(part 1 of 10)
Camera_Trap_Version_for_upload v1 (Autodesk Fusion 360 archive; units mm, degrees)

design "Version_for_upload" references "Button_Board_II", "9Vcell", "DHT11 module", "Half_Bridge", "Gears_Motor2", "Control"
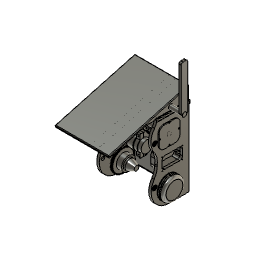
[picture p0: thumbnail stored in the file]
description: Part Number
part number: Contacts
part number: Body
part number: Body003 (Mirror #1)
part number: Contacts (Mirror #1)
part number: Resistor-1206
part number: Body001
part number: Overcoat
part number: Body002
description: KiCad electronic assembly
part number: Button_Board_II 1
part number: PinSocket-01x06_P2.54mm_Horizontal_SMD
parameter "Lower_Gear_Position" = 70
parameter "Inter_Gear_Dist" = 63
parameter "Mid_Gear_Position" = 133 (= "Lower_Gear_Position + Inter_Gear_Dist")
parameter "High_Gear_Position" = 196 (= "Lower_Gear_Position + Inter_Gear_Dist * 2")
parameter "Distance_From_Half_Gear" = 3
parameter "LL_Pin_Length" = 16
parameter "LL_Pin_half_height" = 4.1
parameter "LL_lip_length" = 2
parameter "LL_lip_half_height" = 5
parameter "LL_paper_holding_rod_diam" = 15
parameter "Radius_slidder" = 22.4
parameter "Coil_Diam" = 60
parameter "d371" = 4.1
sketch "Tests" plane through (0, 0, 0) normal (0, 1, 0) x axis (1, 0, 0)
  line L1 (-90.0224, 3) -> (-90.0224, 5)
  line L2 (-29.5204, 3) -> (-20.5451, 3)
  line L3 (-29.5204, 4.2) -> (-29.5204, 3)
  line L4 (-20.5451, 4.2) -> (-29.5204, 4.2)
  line L5 (-20.5451, 3) -> (-20.5451, 4.2)
  line L6 (138, -125) -> (75, -125)
  line L7 (137.8, -100) -> (75, -100)
  line L8 (137.6, -75) -> (75, -75)
  line L9 (137.4, -50) -> (75, -50)
  line L10 (160, -140) -> (55, -140)
  line L11 (160, -35) -> (160, -140)
  line L12 (55, -35) -> (160, -35)
  line L13 (55, -140) -> (55, -35)
  line L14 (250, -180) -> (250, -200)
  line L15 (255, -200) -> (250, -200)
  line L16 (255, -195) -> (255, -200)
  line L17 (260, -195) -> (255, -195)
  line L18 (278.1262, -186.5476) -> (260, -195)
  line L19 (280, -195) -> (260, -195)
  line L20 (278.1262, -180) -> (278.1262, -186.5476)
  line L21 (250, -180) -> (278.1262, -180)
  line L22 (303, -200) -> (300, -200)
  line L23 (303, -180) -> (303, -200)
  line L24 (300, -180) -> (303, -180)
  line L25 (300, -200) -> (300, -180)
  line L26 (306, -197) -> (303, -197)
  line L27 (306, -180) -> (306, -197)
  line L28 (303, -180) -> (306, -180)
  line L29 (303, -197) -> (303, -180)
  line L30 (323, -200) -> (320, -200)
  line L31 (323, -180) -> (323, -200)
  line L32 (320, -180) -> (323, -180)
  line L33 (320, -200) -> (320, -180)
  line L34 (326, -196) -> (323, -196)
  line L35 (326, -180) -> (326, -196)
  line L36 (323, -180) -> (326, -180)
  line L37 (323, -196) -> (323, -180)
  line L38 (250, -145) -> (250, -165)
  line L39 (255, -165) -> (250, -165)
  line L40 (255, -161) -> (255, -165)
  line L41 (260, -161) -> (255, -161)
  line L42 (278.1262, -152.5476) -> (260, -161)
  line L43 (278.1262, -145) -> (278.1262, -152.5476)
  line L44 (250, -145) -> (278.1262, -145)
  line L45 (370.5, -4.2) -> (370.5, -0.1)
  line L46 (375.5, -4.2) -> (370.5, -4.2)
  line L47 (375.5, -17.6) -> (375.5, -4.2)
  line L48 (431, -17.6) -> (375.5, -17.6)
  line L49 (431, 4) -> (431, -17.6)
  line L50 (491.5, -4.2) -> (491.5, -0.1)
  line L51 (486.5, -4.2) -> (491.5, -4.2)
  line L52 (486.5, -17.6) -> (486.5, -4.2)
  line L53 (431, -17.6) -> (486.5, -17.6)
  line L54 (491.5, -0.1) -> (370.5, -0.1)
  line L55 (486.5, 9.15) -> (491.5, 9.15)
  line L56 (481.5, 9.15) -> (491.5, 9.15)
  line L57 (481.5, -0.1) -> (481.5, 9.15)
  line L58 (380.5, 29.9) -> (481.5, 29.9)
  line L59 (380.5, -30.1) -> (380.5, 29.9)
  line L60 (481.5, -30.1) -> (380.5, -30.1)
  line L61 (481.5, 29.9) -> (481.5, -30.1)
  line L62 (380.5, -30.1) -> (481.5, 29.9)
  line L63 (481.5, -30.1) -> (380.5, 29.9)
  line L64 (20, -270) -> (110, -270)
  line L65 (20, -240) -> (20, -270)
  line L66 (110, -230) -> (30, -230)
  line L67 (120, -260) -> (120, -240)
  line L68 (225, -125) -> (190, -125)
  line L69 (225, -65) -> (225, -125)
  line L70 (190, -65) -> (225, -65)
  line L71 (190, -125) -> (190, -65)
  line L72 (205.05, -72) -> (195, -72)
  line L73 (205.05, -117) -> (205.05, -72)
  line L74 (195, -117) -> (205.05, -117)
  line L75 (195, -72) -> (195, -117)
  line L76 (219.9297, -117) -> (209.8297, -117)
  line L77 (219.9297, -72) -> (219.9297, -117)
  line L78 (209.8297, -72) -> (219.9297, -72)
  line L79 (209.8297, -117) -> (209.8297, -72)
  circle C1 centre (20, 0) radius 11
  circle C2 centre (20, 0) radius 12
  circle C3 centre (20, 0) radius 5
  circle C4 centre (-25, 0) radius 4.1
  circle C5 centre (-25, 0) radius 4.15
  circle C6 centre (-25.0614, 0.0651) radius 6
  circle C7 centre (70, 0) radius 17.4
  circle C8 centre (70, 0) radius 18.9
  circle C9 centre (114, 0) radius 18.9
  circle C10 centre (114, 0) radius 17
  circle C11 centre (161, 0) radius 18.9
  circle C12 centre (161, 0) radius 17.1
  circle C13 centre (203, 0) radius 18.9
  circle C14 centre (203, 0) radius 17.15
  circle C15 centre (75, -125) radius 11.05
  circle C16 centre (138, -125) radius 11.05
  circle C17 centre (75, -100) radius 11.05
  circle C18 centre (137.8, -100) radius 11.05
  circle C19 centre (75, -75) radius 11.05
  circle C20 centre (137.6, -75) radius 11.05
  circle C21 centre (75, -50) radius 11.05
  circle C22 centre (137.4, -50) radius 11.05
  circle C23 centre (100, -250) radius 11.1
  circle C24 centre (100, -250) radius 12.75
  circle C25 centre (70, -250) radius 11.15
  circle C26 centre (70, -250) radius 12.8
  circle C27 centre (40, -250) radius 11.2
  circle C28 centre (40, -250) radius 12.85
  arc A1 centre (110, -260) radius 10 clockwise from (120, -260) to (110, -270)
  arc A2 centre (110, -240) radius 10 clockwise from (110, -230) to (120, -240)
  arc A3 centre (30, -240) radius 10 clockwise from (20, -240) to (30, -230)
  point P22 (75, -125)
  point P23 (75, -125)
  point P24 (138, -125)
  point P25 (138, -125)
  point P26 (75, -100)
  point P27 (75, -100)
  point P28 (137.8, -100)
  point P29 (137.8, -100)
  point P30 (75, -75)
  point P31 (75, -75)
  point P32 (137.6, -75)
  point P33 (137.6, -75)
  point P34 (75, -50)
  point P35 (75, -50)
  point P36 (137.4, -50)
  point P37 (137.4, -50)
  point P54 (303, -197)
  point P62 (323, -196)
  point P73 (370.5, -0.1)
  point P80 (491.5, -0.1)
  point P74 (370.5, -4.2)
  point P81 (491.5, -4.2)
  point P75 (375.5, -4.2)
  point P79 (486.5, -4.2)
  point P76 (375.5, -17.6)
  point P82 (486.5, -17.6)
  point P77 (431, -17.6)
  point P83 (431, -17.6)
  point P78 (431, 4)
  point P87 (431, 4)
  point P88 (481.5, -0.1)
  point P93 (431, -0.1)
  point P45 (260, -195)
  point P46 (278.1262, -186.5476)
  point P50 (300, -200)
  point P51 (303, -200)
  point P66 (250, -165)
  point P67 (250, -145)
  point P70 (260, -161)
  point P71 (278.1262, -152.5476)
  point P84 (491.5, 9.15)
  point P86 (481.5, 9.15)
  point P91 (380.5, -30.1)
  point P92 (481.5, -30.1)
  point P90 (380.5, 29.9)
  point P110 (190, -125)
  point P111 (225, -125)
  point P113 (190, -65)
  point P114 (195, -72)
  point P115 (205.05, -72)
  point P117 (195, -117)
  point P118 (209.8297, -117)
  point P119 (219.9297, -117)
  point P121 (209.8297, -72)
  vertical L1
  concentric C1 C2
  concentric C1 C3
  horizontal L2
  vertical L3
  horizontal L4
  vertical L5
  concentric C4 C5
  concentric C7 C8
  concentric C9 C10
  concentric C11 C12
  concentric C13 C14
  coincident P22 P23
  horizontal L6
  coincident P24 P25
  coincident P26 P27
  horizontal L7
  coincident P28 P29
  coincident P30 P31
  horizontal L8
  coincident P32 P33
  coincident P34 P35
  horizontal L9
  coincident P36 P37
  horizontal L10
  vertical L11
  horizontal L12
  vertical L13
  vertical L14
  perpendicular L14 L15
  perpendicular L15 L16
  perpendicular L14 L17
  horizontal L19
  vertical L20
  horizontal L22
  vertical L23
  horizontal L24
  vertical L25
  horizontal L26
  vertical L27
  horizontal L28
  vertical L29
  coincident L23 P54
  horizontal L30
  vertical L31
  horizontal L32
  vertical L33
  horizontal L34
  vertical L35
  horizontal L36
  vertical L37
  coincident L31 P62
  vertical L38
  perpendicular L38 L39
  perpendicular L39 L40
  perpendicular L40 L41
  vertical L43
  vertical L45
  perpendicular L45 L46
  perpendicular L46 L47
  perpendicular L47 L48
  perpendicular L48 L49
  symmetric P73 L49 P80
  symmetric P74 L49 P81
  symmetric P75 L49 P79
  symmetric P76 L49 P82
  symmetric P77 L49 P83
  perpendicular L50 L55
  parallel L55 L56
  coincident P78 P87
  coincident L54 P88
  horizontal L58
  perpendicular L58 L59
  parallel L58 L60
  parallel L59 L61
  coincident L62 P93
  coincident L63 P93
  midpoint L54 P93
  concentric C23 C24
  concentric C25 C26
  concentric C27 C28
  horizontal L64
  vertical L65
  horizontal L66
  vertical L67
  tangent L64 A1
  tangent L67 A1
  tangent L67 A2
  tangent L66 A2
  equal A1 A2
  tangent L66 A3
  tangent L65 A3
  equal A1 A3
  horizontal L68
  vertical L69
  horizontal L70
  vertical L71
  horizontal L72
  vertical L73
  horizontal L74
  vertical L75
  horizontal L76
  vertical L77
  horizontal L78
  vertical L79
  dimension "d7" diameter C1 = 22
  dimension "d8" diameter C2 = 24
  dimension "d13" diameter C3 = 10
  dimension "d45" diameter C4 = 8.2
  dimension "d46" diameter C5 = 8.3
  dimension "d47" diameter C6 = 12
  dimension "d232" diameter C7 = 34.8
  dimension "d233" diameter C8 = 37.8
  dimension "d236" diameter C9 = 37.8
  dimension "d237" diameter C10 = 34
  dimension "d238" diameter C11 = 37.8
  dimension "d239" diameter C12 = 34.2
  dimension "d240" diameter C13 = 37.8
  dimension "d241" diameter C14 = 34.3
  dimension "d299" diameter C15 = 22.1
  dimension "d300" distance P23 P24 = 63
  dimension "d301" diameter C16 = 22.1
  dimension "d302" diameter C17 = 22.1
  dimension "d303" distance P27 P28 = 62.8
  dimension "d304" diameter C18 = 22.1
  dimension "d305" diameter C19 = 22.1
  dimension "d306" distance P31 P32 = 62.6
  dimension "d307" diameter C20 = 22.1
  dimension "d308" diameter C21 = 22.1
  dimension "d309" distance P35 P36 = 62.4
  dimension "d310" diameter C22 = 22.1
  dimension "d323" angle L18 L19 = 25
  dimension "d324" distance P45 P46 = 20
  dimension "d326" distance P50 P51 = 3
  dimension "d331" distance P66 P67 = 20
  dimension "d332" angle L41 L42 = 25
  dimension "d333" distance P70 P71 = 20
  dimension "d555" distance P73 P74 = 4.1
  dimension "d556" distance P74 P75 = 5
  dimension "d557" distance P75 P76 = 13.4
  dimension "d558" distance P76 P77 = 55.5
  dimension "d563" distance P84 P86 = 10
  dimension "d566" distance P91 P92 = 101
  dimension "d567" distance P90 P91 = 60
  dimension "d599" diameter C23 = 22.2
  dimension "d600" diameter C24 = 25.5
  dimension "d601" diameter C25 = 22.3
  dimension "d602" diameter C26 = 25.6
  dimension "d603" diameter C27 = 22.4
  dimension "d604" diameter C28 = 25.7
  dimension "d609" radius A1 = 10
  dimension "d631" distance P110 P111 = 35
  dimension "d632" distance P110 P113 = 60
  dimension "d633" distance P114 P115 = 10.05
  dimension "d634" distance P114 P117 = 45
  dimension "d635" distance P118 P119 = 10.1
  dimension "d636" distance P118 P121 = 45
extrude "Extrude25" new body sketch "Tests" profile of C23 C24 C25 C26 C27 C28 L64 L65 L66 L67 A1 A2 A3 along normal blind 3
extrude "Extrude26" new body sketch "Tests" profile of C23 C24 C25 C26 C27 C28 along normal blind 7
combine "Combine4"
combine "Combine5"
extrude "Extrude27" add sketch "Tests" profile of C23 C24 C25 C26 C27 C28 L64 L65 L66 L67 A1 A2 A3 against normal blind 3
extrude "Extrude11" new body sketch "Tests" profile of C4 L2 along normal blind 20 bodies "Screw"
extrude "Extrude12" new body sketch "Tests" profile of C4 L2 L3 L4 L5 C5 C6 along normal blind 5
extrude "Extrude13" new body sketch "Tests" profile of C4 L2 L3 L4 L5 C5 C6 against normal blind 3 bodies "Nut"
combine "Combine2"
sketch "Line_to_place_gears" plane through (0, 0, 0) normal (1, 0, 0) x axis (0, 1, 0)
  line L1 (0, 70) -> (0, 0)
  line L2 (0, 133) -> (0, 0)
  line L3 (0, 196) -> (0, 0)
  point P1 (0, 0)
  point P2 (0, 0)
  point P4 (0, 0)
  point P6 (0, 0)
  point P3 (0, 70)
  point P5 (0, 133)
  point P7 (0, 196)
  coincident P1 P2
  vertical L1
  coincident P1 P4
  parallel L1 L2
  coincident P1 P6
  parallel L1 L3
  dimension "d55" distance P2 P3 = 70 (= "Lower_Gear_Position")
  dimension "d59" distance P4 P5 = 133 (= "Mid_Gear_Position")
  dimension "d61" distance P6 P7 = 196 (= "High_Gear_Position")
sketch "Teeth" plane through (0, 0, 0) normal (0, 0, 1) x axis (1, 0, 0)
  curve K1 (31.9963, -0.4887) -> (29.9991, -0.9267)
  curve K2 (31.9963, 0.4887) -> (29.9991, 0.9267)
  curve K3 (29.9991, -0.9267) -> (29.9983, -0.9266)
  curve K4 (29.9991, 0.9267) -> (29.9983, 0.9266)
  line L1 (29.9983, -0.9266) -> (0, 0)
  line L2 (29.9983, 0.9266) -> (0, 0)
  line L3 (0, 0) -> (0, 0)
  line L4 (0, 0) -> (0, 0)
  arc A1 centre (0, 0) radius 32 clockwise from (31.9963, 0.4887) to (31.9963, -0.4887)
sketch "Circle" plane through (0, 0, 0) normal (0, 0, 1) x axis (1, 0, 0)
  circle C1 centre (0, 0) radius 29.75
extrude "Extrude1" new body sketch "Circle" along normal blind 3 bodies "Lower_gear"
sweep "Sweep1" sketch "Teeth" TwistAngle 1.5 TaperAngle 0
circular_pattern "C-Pattern1" countU 62 TotalAngle 360
combine "Combine1"
work_plane "WorkPlane1" AlongDistance 3
mirror "Mirror1" mirrorStitchTolerance 0.01
combine "Combine2"
sketch "Label" plane through (0, 0, 0) normal (0, 0, 1) x axis (1, 0, 0)
  curve K1 (87.334, 0) -> (0, 0)
  curve K2 (87.334, 3) -> (87.334, 0)
  curve K3 (0, 3) -> (87.334, 3)
  curve K4 (0, 0) -> (0, 3)
  perpendicular K1 K2
  parallel K1 K3
  parallel K2 K4
sketch "Sketch1" plane through (0, 0, 0) normal (0, 0, 1) x axis (1, 0, 0)
  curve K1 (31.9963, -0.4887) -> (29.9991, -0.9267)
  curve K2 (31.9963, 0.4887) -> (29.9991, 0.9267)
  curve K3 (29.9991, -0.9267) -> (29.9983, -0.9266)
  curve K4 (29.9991, 0.9267) -> (29.9983, 0.9266)
  line L1 (29.9983, -0.9266) -> (0, 0)
  line L2 (29.9983, 0.9266) -> (0, 0)
  line L3 (0, 0) -> (0, 0)
  line L4 (0, 0) -> (0, 0)
  arc A1 centre (0, 0) radius 32 clockwise from (31.9963, 0.4887) to (31.9963, -0.4887)
sketch "Sketch2" plane through (0, 0, 0) normal (0, 0, 1) x axis (1, 0, 0)
  circle C1 centre (0, 0) radius 29.75
extrude "Extrude1" new body sketch "Sketch2" along normal blind 3 bodies "Mid_gear"
sweep "Sweep1" sketch "Sketch1" TwistAngle 1.5 TaperAngle 0
circular_pattern "C-Pattern1" countU 62 TotalAngle 360
combine "Combine1"
work_plane "WorkPlane1" AlongDistance 3
mirror "Mirror1" mirrorStitchTolerance 0.01
combine "Combine2"
sketch "Sketch3" plane through (0, 0, 0) normal (0, 0, 1) x axis (1, 0, 0)
  curve K1 (87.334, 0) -> (0, 0)
  curve K2 (87.334, 3) -> (87.334, 0)
  curve K3 (0, 3) -> (87.334, 3)
  curve K4 (0, 0) -> (0, 3)
  perpendicular K1 K2
  parallel K1 K3
  parallel K2 K4
position "Position1"
sketch "LL_pin" plane through (0, 0, 0) normal (0, 1, 0) x axis (1, 0, 0)
  line L1 (200, 0) -> (-200, 0)
  line L2 (0, -70) -> (0, 0)
  line L3 (-11, -70) -> (5, -70)
  line L4 (-11, -74.1) -> (-11, -70)
  line L5 (5, -70) -> (5, -74.1)
  line L6 (-5, -70) -> (-3, -70)
  line L7 (-5, -75) -> (-5, -74.1)
  line L8 (-3, -75) -> (-5, -75)
  line L9 (-3, -74.1) -> (-3, -75)
  line L10 (-5, -74.1) -> (-11, -74.1)
  line L11 (5, -74.1) -> (-3, -74.1)
  point P1 (0, 0)
  point P4 (0, 0)
  point P10 (-3, -70)
  point P2 (-200, 0)
  point P3 (200, 0)
  point P5 (0, -70)
  point P6 (5, -70)
  point P7 (-11, -70)
  point P9 (5, -74.1)
  point P11 (-5, -70)
  point P13 (-3, -75)
  horizontal L1
  coincident P1 P4
  perpendicular L1 L2
  horizontal L3
  vertical L4
  horizontal L10
  vertical L5
  horizontal L6
  vertical L7
  horizontal L8
  vertical L9
  midpoint L3 P10
  collinear L10 L11
  dimension "d120" distance P2 P3 = 400
  dimension "d122" distance P4 P5 = 70
  dimension "d123" distance P6 P7 = 16 (= "LL_Pin_Length")
  dimension "d124" distance P6 P9 = 4.1 (= "LL_Pin_half_height")
  dimension "d129" distance P10 P11 = 2 (= "LL_lip_length")
  dimension "d130" distance P10 P13 = 5 (= "LL_lip_half_height")
revolve "Revolve1" sketch "LL_pin" AlongAngle 360 bodies "S1_L_Pin"
sketch "LL_pin_falt_face" plane through (5, 0, 0) normal (1, 0, 0) x axis (0, 1, 0)
  line L1 (0, 67) -> (0, 70)
  line L2 (2.8039, 67.0087) -> (-2.8039, 67.0087)
  circle C1 centre (0, 70) radius 4.1
  point P2 (0, 70)
  point P3 (0, 70)
  point P5 (-2.8039, 67.0087)
  point P6 (2.8039, 67.0087)
  coincident P2 P3
  vertical L1
  coincident C1 P5
  coincident C1 P6
  perpendicular L1 L2
extrude "Extrude1" cut sketch "LL_pin_falt_face" profile of C1 L2 against normal blind 5
fillet "Fillet1" radius 1
extrude "Extrude2" new body sketch "Tests" profile of C1 C2 along normal blind 9 bodies "Ball_holder"
extrude "Extrude3" add sketch "Tests" profile of C1 C2 against normal blind 2
extrude "Extrude4" add sketch "Tests" profile of C3 along normal blind 2
sketch "LL_pin" plane through (0, 0, 0) normal (0, 1, 0) x axis (1, 0, 0)
  line L1 (200, 0) -> (-200, 0)
  line L2 (0, -70) -> (0, 0)
  line L3 (-11, -70) -> (5, -70)
  line L4 (-11, -74.1) -> (-11, -70)
  line L5 (5, -70) -> (5, -74.1)
  line L6 (-5, -70) -> (-3, -70)
  line L7 (-5, -75) -> (-5, -74.1)
  line L8 (-3, -75) -> (-5, -75)
  line L9 (-3, -74.1) -> (-3, -75)
  line L10 (-5, -74.1) -> (-11, -74.1)
  line L11 (5, -74.1) -> (-3, -74.1)
  point P1 (0, 0)
  point P4 (0, 0)
  point P10 (-3, -70)
  point P2 (-200, 0)
  point P3 (200, 0)
  point P5 (0, -70)
  point P6 (5, -70)
  point P7 (-11, -70)
  point P9 (5, -74.1)
  point P11 (-5, -70)
  point P13 (-3, -75)
  horizontal L1
  coincident P1 P4
  perpendicular L1 L2
  horizontal L3
  vertical L4
  horizontal L10
  vertical L5
  horizontal L6
  vertical L7
  horizontal L8
  vertical L9
  midpoint L3 P10
  collinear L10 L11
  dimension "d120_1" distance P2 P3 = 400
  dimension "d122_1" distance P4 P5 = 70
  dimension "d123_1" distance P6 P7 = 16 (= "LL_Pin_Length")
  dimension "d124_1" distance P6 P9 = 4.1 (= "LL_Pin_half_height")
  dimension "d129_1" distance P10 P11 = 2 (= "LL_lip_length")
  dimension "d130_1" distance P10 P13 = 5 (= "LL_lip_half_height")
revolve "Revolve1" sketch "LL_pin" AlongAngle 360 named "d131_1" bodies "S1_L_Pin_cutting_tool"
sketch "Cutting_Tool_Nut" plane through (5, 0, 0) normal (1, 0, 0) x axis (0, 1, 0)
  line L1 (0, 67) -> (0, 70)
  line L2 (2.8039, 67.0087) -> (-2.8039, 67.0087)
  circle C1 centre (0, 70) radius 4.1
  point P2 (0, 70)
  point P3 (0, 70)
  point P5 (-2.8039, 67.0087)
  point P6 (2.8039, 67.0087)
  coincident P2 P3
  vertical L1
  coincident C1 P5
  coincident C1 P6
  perpendicular L1 L2
extrude "Extrude1" cut sketch "Cutting_Tool_Nut" profile of C1 L2 against normal blind 5 named "d132_1"
fillet "Fillet1" radius 1 named "d135_1"
offset_faces "OffsetFaces1" distance 0.001
sketch "Sketch2" plane through (5, 0, 0) normal (1, 0, 0) x axis (0, 1, 0)
  line L1 (2.8054, 67.0087) -> (-2.8054, 67.0087)
  arc A1 centre (0, 70) radius 4.101 clockwise from (-2.8054, 67.0087) to (2.8054, 67.0087)
  circle C1 centre (0, 70) radius 5.5
  concentric A1 C1
  dimension "d137" diameter C1 = 11
extrude "Extrude1" new body sketch "Sketch2" against normal blind 5
extrude "Extrude2" add of existing geometry blind 2
combine "Combine1"
copy_paste_bodies "CutPasteBodies1"
sketch "Cilinder" plane through (6, 0, 0) normal (1, 0, 0) x axis (0, 1, 0)
  line L1 (-5.1309, 99.5707) -> (-5.086, 99.312)
  line L2 (-5.1311, 99.5716) -> (-5.1309, 99.5707)
  curve K1 (-5.9621, 101.4397) -> (-5.1311, 99.5716)
  curve K2 (-6.9195, 101.2429) -> (-6.9465, 99.1985)
  line L3 (-6.9465, 99.1985) -> (-6.9463, 99.1977)
  line L4 (-6.8855, 98.9422) -> (-6.9463, 99.1977)
  line L5 (-8.0962, 98.8999) -> (-8.0254, 98.6471)
  line L6 (-8.0965, 98.9008) -> (-8.0962, 98.8999)
  curve K3 (-9.1122, 100.6752) -> (-8.0965, 98.9008)
  curve K4 (-10.0448, 100.3826) -> (-9.8648, 98.3459)
  line L7 (-9.8648, 98.3459) -> (-9.8645, 98.3451)
  line L8 (-9.7782, 98.0971) -> (-9.8645, 98.3451)
  line L9 (-10.9784, 97.9326) -> (-10.8824, 97.6882)
  line L10 (-10.9788, 97.9334) -> (-10.9784, 97.9326)
  curve K5 (-12.1688, 99.5959) -> (-10.9788, 97.9334)
  curve K6 (-13.067, 99.2105) -> (-12.6819, 97.2025)
  line L11 (-12.6819, 97.2025) -> (-12.6815, 97.2017)
  line L12 (-12.5706, 96.9637) -> (-12.6815, 97.2017)
  line L13 (-13.748, 96.6786) -> (-13.6277, 96.4452)
  line L14 (-13.7484, 96.6793) -> (-13.748, 96.6786)
  curve K7 (-15.1006, 98.213) -> (-13.7484, 96.6793)
  curve K8 (-15.9551, 97.7387) -> (-15.3689, 95.7799)
  line L15 (-15.3689, 95.7799) -> (-15.3684, 95.7792)
  line L16 (-15.234, 95.5536) -> (-15.3684, 95.7792)
  line L17 (-16.3765, 95.1508) -> (-16.2332, 94.9308)
  line L18 (-16.377, 95.1516) -> (-16.3765, 95.1508)
  curve K9 (-17.8773, 96.5405) -> (-16.377, 95.1516)
  curve K10 (-18.6796, 95.9822) -> (-17.8981, 94.0928)
  line L19 (-17.8981, 94.0928) -> (-17.8976, 94.0921)
  line L20 (-17.741, 93.8813) -> (-17.8976, 94.0921)
  line L21 (-18.8369, 93.365) -> (-18.6721, 93.1606)
  line L22 (-18.8375, 93.3657) -> (-18.8369, 93.365)
  curve K11 (-20.4707, 94.5958) -> (-18.8375, 93.3657)
  curve K12 (-21.2123, 93.9591) -> (-20.2437, 92.1585)
  line L23 (-20.2437, 92.1585) -> (-20.2431, 92.1578)
  line L24 (-20.066, 91.964) -> (-20.2431, 92.1578)
  line L25 (-21.1041, 91.3394) -> (-20.9195, 91.1527)
  line L26 (-21.1047, 91.34) -> (-21.1041, 91.3394)
  curve K13 (-22.854, 92.3986) -> (-21.1047, 91.34)
  curve K14 (-23.5274, 91.6902) -> (-22.3816, 89.9968)
  line L27 (-22.3816, 89.9968) -> (-22.381, 89.9962)
  line L28 (-22.1852, 89.8212) -> (-22.381, 89.9962)
  line L29 (-23.1547, 89.0949) -> (-22.9521, 88.9278)
  line L30 (-23.1554, 89.0954) -> (-23.1547, 89.0949)
  curve K15 (-25.0027, 89.9716) -> (-23.1554, 89.0954)
  curve K16 (-25.601, 89.1987) -> (-24.2898, 87.6299)
  line L31 (-24.2898, 87.6299) -> (-24.2891, 87.6293)
  line L32 (-24.0766, 87.4751) -> (-24.2891, 87.6293)
  line L33 (-24.9677, 86.6544) -> (-24.7493, 86.5087)
  line L34 (-24.9684, 86.6549) -> (-24.9677, 86.6544)
  curve K17 (-26.8949, 87.3396) -> (-24.9684, 86.6549)
  curve K18 (-27.412, 86.5101) -> (-25.9488, 85.082)
  line L35 (-25.9488, 85.082) -> (-25.948, 85.0816)
  line L36 (-25.721, 84.9497) -> (-25.948, 85.0816)
  line L37 (-26.5245, 84.043) -> (-26.2924, 83.9202)
  line L38 (-26.5252, 84.0434) -> (-26.5245, 84.043)
  curve K19 (-28.5112, 84.5297) -> (-26.5252, 84.0434)
  curve K20 (-28.9416, 83.6522) -> (-27.3414, 82.3795)
  line L39 (-27.3414, 82.3795) -> (-27.3407, 82.3791)
  line L40 (-27.1015, 82.2708) -> (-27.3407, 82.3791)
  line L41 (-27.8091, 81.2875) -> (-27.5658, 81.1888)
  line L42 (-27.8099, 81.2878) -> (-27.8091, 81.2875)
  curve K21 (-29.8348, 81.5708) -> (-27.8099, 81.2878)
  curve K22 (-30.1743, 80.6542) -> (-28.4536, 79.5499)
  line L43 (-28.4536, 79.5499) -> (-28.4528, 79.5496)
  line L44 (-28.2038, 79.466) -> (-28.4528, 79.5496)
  line L45 (-28.8084, 78.4162) -> (-28.5563, 78.3426)
  line L46 (-28.8092, 78.4164) -> (-28.8084, 78.4162)
  curve K23 (-30.8524, 78.493) -> (-28.8092, 78.4164)
  curve K24 (-31.0973, 77.5468) -> (-29.2737, 76.6223)
  line L47 (-29.2737, 76.6223) -> (-29.2729, 76.6221)
  line L48 (-29.0168, 76.5641) -> (-29.2729, 76.6221)
  line L49 (-29.512, 75.4585) -> (-29.2538, 75.4108)
  line L50 (-29.5129, 75.4587) -> (-29.512, 75.4585)
  curve K25 (-31.5533, 75.3282) -> (-29.5129, 75.4587)
  curve K26 (-31.7013, 74.3621) -> (-29.7935, 73.6267)
  line L51 (-29.7935, 73.6267) -> (-29.7927, 73.6266)
  line L52 (-29.532, 73.5949) -> (-29.7927, 73.6266)
  line L53 (-29.9128, 72.4448) -> (-29.6511, 72.4235)
  line L54 (-29.9137, 72.4449) -> (-29.9128, 72.4448)
  curve K27 (-31.9304, 72.1087) -> (-29.9137, 72.4449)
  curve K28 (-31.98, 71.1325) -> (-30.0076, 70.5939)
  line L55 (-30.0076, 70.5939) -> (-30.0067, 70.5939)
  line L56 (-29.7442, 70.5887) -> (-30.0067, 70.5939)
  line L57 (-30.0067, 69.4061) -> (-29.7442, 69.4113)
  line L58 (-30.0076, 69.4061) -> (-30.0067, 69.4061)
  curve K29 (-31.98, 68.8675) -> (-30.0076, 69.4061)
  curve K30 (-31.9304, 67.8913) -> (-29.9137, 67.5551)
  line L59 (-29.9137, 67.5551) -> (-29.9128, 67.5552)
  line L60 (-29.6511, 67.5765) -> (-29.9128, 67.5552)
  line L61 (-29.7927, 66.3734) -> (-29.532, 66.4051)
  line L62 (-29.7935, 66.3733) -> (-29.7927, 66.3734)
  curve K31 (-31.7013, 65.6379) -> (-29.7935, 66.3733)
  curve K32 (-31.5533, 64.6718) -> (-29.5129, 64.5413)
  line L63 (-29.5129, 64.5413) -> (-29.512, 64.5415)
  line L64 (-29.2538, 64.5892) -> (-29.512, 64.5415)
  line L65 (-29.2729, 63.3779) -> (-29.0168, 63.4359)
  line L66 (-29.2737, 63.3777) -> (-29.2729, 63.3779)
  curve K33 (-31.0973, 62.4532) -> (-29.2737, 63.3777)
  curve K34 (-30.8524, 61.507) -> (-28.8092, 61.5836)
  line L67 (-28.8092, 61.5836) -> (-28.8084, 61.5838)
  line L68 (-28.5563, 61.6574) -> (-28.8084, 61.5838)
  line L69 (-28.4528, 60.4504) -> (-28.2038, 60.534)
  line L70 (-28.4536, 60.4501) -> (-28.4528, 60.4504)
  curve K35 (-30.1743, 59.3458) -> (-28.4536, 60.4501)
  curve K36 (-29.8348, 58.4292) -> (-27.8099, 58.7122)
  line L71 (-27.8099, 58.7122) -> (-27.8091, 58.7125)
  line L72 (-27.5658, 58.8112) -> (-27.8091, 58.7125)
  line L73 (-27.3407, 57.6209) -> (-27.1015, 57.7292)
  line L74 (-27.3414, 57.6205) -> (-27.3407, 57.6209)
  curve K37 (-28.9416, 56.3478) -> (-27.3414, 57.6205)
  curve K38 (-28.5112, 55.4703) -> (-26.5252, 55.9566)
  line L75 (-26.5252, 55.9566) -> (-26.5245, 55.957)
  line L76 (-26.2924, 56.0798) -> (-26.5245, 55.957)
  line L77 (-25.948, 54.9184) -> (-25.721, 55.0503)
  line L78 (-25.9488, 54.918) -> (-25.948, 54.9184)
  curve K39 (-27.412, 53.4899) -> (-25.9488, 54.918)
  curve K40 (-26.8949, 52.6604) -> (-24.9684, 53.3451)
  line L79 (-24.9684, 53.3451) -> (-24.9677, 53.3456)
  line L80 (-24.7493, 53.4913) -> (-24.9677, 53.3456)
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  dimension "d142" diameter = 15 (= "LL_paper_holding_rod_diam")
extrude "Extrude1" new body sketch "Cilinder" along normal blind 10 bodies "Gear_Holder_Coupling"
sketch "paper_holder" plane through (0, 0, 0) normal (0, 1, 0) x axis (1, 0, 0)
  line L1 (16, -74.1) -> (16, -77.5)
  line L2 (11, -74.1) -> (16, -74.1)
  line L3 (11, -70) -> (11, -74.1)
  line L4 (127, -75) -> (129, -75)
  line L5 (127, -77.5) -> (127, -75)
  line L6 (16, -77.5) -> (127, -77.5)
  line L7 (135, -74.1) -> (135, -70)
  line L8 (129, -74.1) -> (135, -74.1)
  line L9 (129, -75) -> (129, -74.1)
  line L10 (150, -70) -> (140, -70)
  line L11 (135, -70) -> (11, -70)
  line L12 (21, -74.1) -> (16, -74.1)
  line L13 (122, -69) -> (122, -71)
  line L14 (21, -71) -> (21, -69)
  line L15 (122, -80) -> (21, -80)
  line L16 (122, -62.5) -> (122, -80)
  line L17 (21, -62.5) -> (122, -62.5)
  line L18 (21, -80) -> (21, -62.5)
  point P2 (16, -77.5)
  point P3 (16, -74.1)
  point P4 (11, -74.1)
  point P5 (129, -75)
  point P6 (127, -75)
  point P7 (127, -77.5)
  point P15 (21, -71)
  point P16 (122, -71)
  point P19 (21, -80)
  point P20 (122, -80)
  point P22 (21, -62.5)
  vertical L1
  perpendicular L1 L2
  perpendicular L2 L3
  perpendicular L4 L5
  parallel L8 L10
  perpendicular L1 L12
  vertical L13
  vertical L14
  horizontal L15
  vertical L16
  horizontal L17
  vertical L18
  dimension "d146" distance P2 P3 = 3.4
  dimension "d147" distance P3 P4 = 5
  dimension "d154" distance P5 P6 = 2
  dimension "d155" distance P6 P7 = 2.5
  dimension "d164" distance P15 P16 = 101
  dimension "d167" distance P19 P20 = 101
  dimension "d168" distance P19 P22 = 17.5
revolve "Revolve1" sketch "paper_holder" AlongAngle 360 bodies "S1_paper_holder"
sketch "cutting_Base" plane through (127, 0, 0) normal (1, 0, 0) x axis (0, 1, 0)
  line L1 (2.3976, 62.8936) -> (-2.3976, 62.8936)
  circle C1 centre (0, 70) radius 5
  circle C2 centre (0, 70) radius 7.5
  point P3 (-2.3976, 62.8936)
  point P4 (2.3976, 62.8936)
  coincident C2 P3
  coincident C2 P4
  horizontal L1
extrude "Extrude1" cut sketch "cutting_Base" profile of C2 L1 against normal blind 110.1
extrude "Extrude3" cut sketch "paper_holder" profile of L6 L11 L13 L14 L15 L16 L17 L18 distance 1
copy_paste "CutPaste1"
copy_paste "CutPaste1"
sketch "flat_front_pin_base" plane through (11, 0, 0) normal (-1, 0, 0) x axis (0, -1, 0)
  line L1 (0, 70) -> (0, 74.1)
  line L2 (0, 67) -> (0, 70)
  line L3 (2.7971, 67.0023) -> (-2.7971, 67.0023)
  circle C1 centre (0, 70) radius 4.1
  point P3 (0, 74.1)
  point P2 (0, 70)
  point P4 (0, 70)
  point P5 (0, 70)
  point P7 (-2.7971, 67.0023)
  point P8 (2.7971, 67.0023)
  point P6 (0, 67)
  coincident C1 P3
  coincident P2 P4
  vertical L1
  coincident P2 P5
  parallel L1 L2
  coincident C1 P7
  coincident C1 P8
  horizontal L3
  dimension "d175" distance P5 P6 = 3
extrude "Extrude4" cut sketch "flat_front_pin_base" profile of C1 against normal blind 5
sketch "LL_pin" plane through (0, 0, 0) normal (0, 1, 0) x axis (1, 0, 0)
  line L1 (200, 0) -> (-200, 0)
  line L2 (0, -70) -> (0, 0)
  line L3 (-11, -70) -> (5, -70)
  line L4 (-11, -74.1) -> (-11, -70)
  line L5 (5, -70) -> (5, -74.1)
  line L6 (-5, -70) -> (-3, -70)
  line L7 (-5, -75) -> (-5, -74.1)
  line L8 (-3, -75) -> (-5, -75)
  line L9 (-3, -74.1) -> (-3, -75)
  line L10 (-5, -74.1) -> (-11, -74.1)
  line L11 (5, -74.1) -> (-3, -74.1)
  point P1 (0, 0)
  point P4 (0, 0)
  point P10 (-3, -70)
  point P2 (-200, 0)
  point P3 (200, 0)
  point P5 (0, -70)
  point P6 (5, -70)
  point P7 (-11, -70)
  point P9 (5, -74.1)
  point P11 (-5, -70)
  point P13 (-3, -75)
  horizontal L1
  coincident P1 P4
  perpendicular L1 L2
  horizontal L3
  vertical L4
  horizontal L10
  vertical L5
  horizontal L6
  vertical L7
  horizontal L8
  vertical L9
  midpoint L3 P10
  collinear L10 L11
  dimension "d120_2" distance P2 P3 = 400
  dimension "d122_2" distance P4 P5 = 70
  dimension "d123_2" distance P6 P7 = 16 (= "LL_Pin_Length")
  dimension "d124_2" distance P6 P9 = 4.1 (= "LL_Pin_half_height")
  dimension "d129_2" distance P10 P11 = 2 (= "LL_lip_length")
  dimension "d130_2" distance P10 P13 = 5 (= "LL_lip_half_height")
revolve "Revolve1" sketch "LL_pin" AlongAngle 360 named "d131_2" bodies "S1_L_Pin"
sketch "LL_pin_falt_face" plane through (5, 0, 0) normal (1, 0, 0) x axis (0, 1, 0)
  line L1 (0, 67) -> (0, 70)
  line L2 (2.8039, 67.0087) -> (-2.8039, 67.0087)
  circle C1 centre (0, 70) radius 4.1
  point P2 (0, 70)
  point P3 (0, 70)
  point P5 (-2.8039, 67.0087)
  point P6 (2.8039, 67.0087)
  coincident P2 P3
  vertical L1
  coincident C1 P5
  coincident C1 P6
  perpendicular L1 L2
extrude "Extrude1" cut sketch "LL_pin_falt_face" profile of C1 L2 against normal blind 5 named "d132_2"
fillet "Fillet1" radius 1 named "d135_2"
sketch "paper_holder" plane through (0, 0, 0) normal (0, 1, 0) x axis (1, 0, 0)
  line L1 (16, -74.1) -> (16, -77.5)
  line L2 (11, -74.1) -> (16, -74.1)
  line L3 (11, -70) -> (11, -74.1)
  line L4 (127, -75) -> (129, -75)
  line L5 (127, -77.5) -> (127, -75)
  line L6 (16, -77.5) -> (127, -77.5)
  line L7 (135, -74.1) -> (135, -70)
  line L8 (129, -74.1) -> (135, -74.1)
  line L9 (129, -75) -> (129, -74.1)
  line L10 (150, -70) -> (140, -70)
  line L11 (135, -70) -> (11, -70)
  line L12 (21, -74.1) -> (16, -74.1)
  line L13 (122, -69) -> (122, -71)
  line L14 (21, -71) -> (21, -69)
  line L15 (122, -80) -> (21, -80)
  line L16 (122, -62.5) -> (122, -80)
  line L17 (21, -62.5) -> (122, -62.5)
  line L18 (21, -80) -> (21, -62.5)
  point P2 (16, -77.5)
  point P3 (16, -74.1)
  point P4 (11, -74.1)
  point P5 (129, -75)
  point P6 (127, -75)
  point P7 (127, -77.5)
  point P15 (21, -71)
  point P16 (122, -71)
  point P19 (21, -80)
  point P20 (122, -80)
  point P22 (21, -62.5)
  vertical L1
  perpendicular L1 L2
  perpendicular L2 L3
  perpendicular L4 L5
  parallel L8 L10
  perpendicular L1 L12
  vertical L13
  vertical L14
  horizontal L15
  vertical L16
  horizontal L17
  vertical L18
  dimension "d146_1" distance P2 P3 = 3.4
  dimension "d147_1" distance P3 P4 = 5
  dimension "d154_1" distance P5 P6 = 2
  dimension "d155_1" distance P6 P7 = 2.5
  dimension "d164_1" distance P15 P16 = 101
  dimension "d167_1" distance P19 P20 = 101
  dimension "d168_1" distance P19 P22 = 17.5
revolve "Revolve1" sketch "paper_holder" AlongAngle 360 named "d159_1" bodies "S1_paper_holder"
sketch "cutting_Base" plane through (127, 0, 0) normal (1, 0, 0) x axis (0, 1, 0)
  line L1 (2.3976, 62.8936) -> (-2.3976, 62.8936)
  circle C1 centre (0, 70) radius 5
  circle C2 centre (0, 70) radius 7.5
  point P3 (-2.3976, 62.8936)
  point P4 (2.3976, 62.8936)
  coincident C2 P3
  coincident C2 P4
  horizontal L1
extrude "Extrude1" cut sketch "cutting_Base" profile of C2 L1 against normal blind 110.1 named "d160_1"
extrude "Extrude3" cut sketch "paper_holder" profile of L6 L11 L13 L14 L15 L16 L17 L18 distance 1 named "d169_1"
remove_instance "RemoveInstance1"
sketch "flat_front_pin_base" plane through (11, 0, 0) normal (-1, 0, 0) x axis (0, -1, 0)
  line L1 (0, 70) -> (0, 74.1)
  line L2 (0, 67) -> (0, 70)
  line L3 (2.7971, 67.0023) -> (-2.7971, 67.0023)
  circle C1 centre (0, 70) radius 4.1
  point P3 (0, 74.1)
  point P2 (0, 70)
  point P4 (0, 70)
  point P5 (0, 70)
  point P7 (-2.7971, 67.0023)
  point P8 (2.7971, 67.0023)
  point P6 (0, 67)
  coincident C1 P3
  coincident P2 P4
  vertical L1
  coincident P2 P5
  parallel L1 L2
  coincident C1 P7
  coincident C1 P8
  horizontal L3
  dimension "d175_1" distance P5 P6 = 3
extrude "Extrude4" cut sketch "flat_front_pin_base" profile of C1 against normal blind 5 named "d173_1"
offset_faces "OffsetFaces1" distance 0.1
position "Position2"
combine "Combine1"
offset_faces "OffsetFaces1" distance -0.1
sketch "Sketch1" plane through (-11, 0, 0) normal (-1, 0, 0) x axis (0, -1, 0)
  circle C1 centre (0, 70) radius 4.1
  circle C2 centre (0, 70) radius 11
  concentric C1 C2
  dimension "d180" diameter C2 = 22
extrude "Extrude1" new body sketch "Sketch1" along normal blind 1 and against normal blind 6 bodies "L_ball_bearing"
sketch "Sketch1" plane through (135, 0, 0) normal (1, 0, 0) x axis (0, 1, 0)
  circle C1 centre (0, 70) radius 4
  circle C2 centre (0, 70) radius 4.1
  circle C3 centre (0, 70) radius 11
  concentric C1 C2
  concentric C2 C3
  dimension "d185" diameter C2 = 8.2
  dimension "d186" diameter C3 = 22
extrude "Extrude1" new body sketch "Sketch1" profile of C2 C3 blind 7 from offset -6 bodies "Right_ball_bearing"
combine "Combine3"
combine "Combine1" bodies "Lower_gear"
copy_paste "CutPaste1"
copy_paste "CutPaste2"
copy_paste "CutPaste3"
copy_paste "CutPaste4"
copy_paste "CutPaste5"
copy_paste "CutPaste6"
copy_paste "CutPaste7"
copy_paste "CutPaste8"
copy_paste "CutPaste9"
sketch "Sketch1" plane through (136, 0, 0) normal (1, 0, 0) x axis (0, 1, 0)
  line L1 (-15, 45) -> (15, 45)
  line L2 (-25, 85) -> (-25, 55)
  line L3 (15, 95) -> (-15, 95)
  line L4 (25, 55) -> (25, 85)
  line L5 (-25, 95) -> (25, 45)
  line L6 (25, 95) -> (-25, 45)
  line L7 (-28.5355, 91.4645) -> (21.4645, 41.4645)
  line L8 (15, 100) -> (-15, 100)
  line L9 (30, 55) -> (30, 85)
  line L10 (-15, 40) -> (15, 40)
  line L11 (-30, 85) -> (-30, 55)
  circle C1 centre (0, 70) radius 4.1
  circle C2 centre (0, 70) radius 11
  circle C3 centre (0, 70) radius 6.5
  arc A1 centre (-15, 85) radius 10 clockwise from (-25, 85) to (-15, 95)
  arc A2 centre (15, 85) radius 10 clockwise from (15, 95) to (25, 85)
  arc A3 centre (15, 55) radius 10 clockwise from (25, 55) to (15, 45)
  arc A4 centre (-15, 55) radius 10 clockwise from (-15, 45) to (-25, 55)
  circle C4 centre (-27.5, 70) radius 1.65
  circle C5 centre (27.5, 70) radius 1.65
  circle C6 centre (0, 97.5) radius 1.65
  circle C7 centre (0, 42.5) radius 1.65
  circle C8 centre (-27.5, 70) radius 1
  circle C9 centre (0, 97.5) radius 1
  circle C10 centre (27.5, 70) radius 1
  circle C11 centre (0, 42.5) radius 1
  arc A5 centre (-15, 85) radius 15 clockwise from (-28.5355, 91.4645) to (-15, 100)
  arc A6 centre (15, 85) radius 15 clockwise from (15, 100) to (30, 85)
  arc A7 centre (15, 55) radius 15 clockwise from (30, 55) to (21.4645, 41.4645)
  arc A8 centre (15, 55) radius 15 clockwise from (21.4645, 41.4645) to (15, 40)
  arc A9 centre (-15, 55) radius 15 clockwise from (-15, 40) to (-30, 55)
  arc A10 centre (-15, 85) radius 15 clockwise from (-30, 85) to (-28.5355, 91.4645)
  point P8 (0, 70)
  point P3 (0, 70)
  point P6 (-25, 95)
  point P7 (25, 95)
  point P4 (25, 45)
  point P5 (-25, 45)
  concentric C1 C3
  horizontal L1
  perpendicular L1 L2
  parallel L1 L3
  parallel L2 L4
  coincident L5 P8
  coincident L6 P8
  coincident P3 P8
  coincident P6 L3
  coincident P6 L2
  tangent L3 A1
  tangent L2 A1
  coincident P7 L4
  coincident P7 L3
  tangent L4 A2
  tangent L3 A2
  equal A1 A2
  coincident P4 L4
  coincident P4 L1
  tangent L4 A3
  tangent L1 A3
  equal A1 A3
  coincident P5 L1
  coincident P5 L2
  tangent L1 A4
  tangent L2 A4
  equal A1 A4
  concentric C4 C8
  concentric C6 C9
  concentric C5 C10
  concentric C7 C11
  dimension "d190" diameter C3 = 13
  dimension "d191" distance P6 P7 = 50
  dimension "d192" distance P5 P6 = 50
  dimension "d193" radius A1 = 10
  dimension "d200" = -5
  dimension "d203" diameter C4 = 3.3
  dimension "d204" diameter C5 = 3.3
  dimension "d205" diameter C6 = 3.3
  dimension "d206" diameter C7 = 3.3
  dimension "d210" diameter C8 = 2
  dimension "d211" diameter C9 = 2
  dimension "d212" diameter C10 = 2
  dimension "d213" diameter C11 = 2
extrude "Extrude1" new body sketch "Sketch1" profile of C2 C3 L1 L2 L3 L4 A1 A2 A3 A4 along normal blind 2
extrude "Extrude2" new body sketch "Sketch1" profile of C2 L1 L2 L3 L4 A1 A2 A3 A4 against normal blind 7
extrude "Extrude3" new body sketch "Sketch1" profile of C1 C2 C3 L1 L2 L3 L4 A1 A2 A3 A4 L9 L8 A8 L7 A9 L11 L10 A10 A6 along normal blind 3
extrude "Extrude4" cut sketch "Sketch1" profile of C4 C5 C6 C7 blind -1 from offset 3
extrude "Extrude5" cut sketch "Sketch1" profile of C8 C9 C10 C11 along normal blind 2
copy_paste "CutPaste1"
external_derived "ExternalDerived1"
derived_instance "DerivedInstance1"
move "Move1"
move "Move2"
position "Position3"
sketch "Sketch1" plane through (6, 0, 0) normal (1, 0, 0) x axis (0, 1, 0)
  line L1 (-5.1309, 162.5707) -> (-5.086, 162.312)
  line L2 (-5.1311, 162.5716) -> (-5.1309, 162.5707)
  curve K1 (-5.9621, 164.4397) -> (-5.1311, 162.5716)
  curve K2 (-6.9195, 164.2429) -> (-6.9465, 162.1985)
  line L3 (-6.9465, 162.1985) -> (-6.9463, 162.1977)
  line L4 (-6.8855, 161.9422) -> (-6.9463, 162.1977)
  line L5 (-8.0962, 161.8999) -> (-8.0254, 161.6471)
  line L6 (-8.0965, 161.9008) -> (-8.0962, 161.8999)
  curve K3 (-9.1122, 163.6752) -> (-8.0965, 161.9008)
  curve K4 (-10.0448, 163.3826) -> (-9.8648, 161.3459)
  line L7 (-9.8648, 161.3459) -> (-9.8645, 161.3451)
  line L8 (-9.7782, 161.0971) -> (-9.8645, 161.3451)
  line L9 (-10.9784, 160.9326) -> (-10.8824, 160.6882)
  line L10 (-10.9788, 160.9334) -> (-10.9784, 160.9326)
  curve K5 (-12.1688, 162.5959) -> (-10.9788, 160.9334)
  curve K6 (-13.067, 162.2105) -> (-12.6819, 160.2025)
  line L11 (-12.6819, 160.2025) -> (-12.6815, 160.2017)
  line L12 (-12.5706, 159.9637) -> (-12.6815, 160.2017)
  line L13 (-13.748, 159.6786) -> (-13.6277, 159.4452)
  line L14 (-13.7484, 159.6793) -> (-13.748, 159.6786)
  curve K7 (-15.1006, 161.213) -> (-13.7484, 159.6793)
  curve K8 (-15.9551, 160.7387) -> (-15.3689, 158.7799)
  line L15 (-15.3689, 158.7799) -> (-15.3684, 158.7792)
  line L16 (-15.234, 158.5536) -> (-15.3684, 158.7792)
  line L17 (-16.3765, 158.1508) -> (-16.2332, 157.9308)
  line L18 (-16.377, 158.1516) -> (-16.3765, 158.1508)
  curve K9 (-17.8773, 159.5405) -> (-16.377, 158.1516)
  curve K10 (-18.6796, 158.9822) -> (-17.8981, 157.0928)
  line L19 (-17.8981, 157.0928) -> (-17.8976, 157.0921)
  line L20 (-17.741, 156.8813) -> (-17.8976, 157.0921)
  line L21 (-18.8369, 156.365) -> (-18.6721, 156.1606)
  line L22 (-18.8375, 156.3657) -> (-18.8369, 156.365)
  curve K11 (-20.4707, 157.5958) -> (-18.8375, 156.3657)
  curve K12 (-21.2123, 156.9591) -> (-20.2437, 155.1585)
  line L23 (-20.2437, 155.1585) -> (-20.2431, 155.1578)
  line L24 (-20.066, 154.964) -> (-20.2431, 155.1578)
  line L25 (-21.1041, 154.3394) -> (-20.9195, 154.1527)
  line L26 (-21.1047, 154.34) -> (-21.1041, 154.3394)
  curve K13 (-22.854, 155.3986) -> (-21.1047, 154.34)
  curve K14 (-23.5274, 154.6902) -> (-22.3816, 152.9968)
  line L27 (-22.3816, 152.9968) -> (-22.381, 152.9962)
  line L28 (-22.1852, 152.8212) -> (-22.381, 152.9962)
  line L29 (-23.1547, 152.0949) -> (-22.9521, 151.9278)
  line L30 (-23.1554, 152.0954) -> (-23.1547, 152.0949)
  curve K15 (-25.0027, 152.9716) -> (-23.1554, 152.0954)
  curve K16 (-25.601, 152.1987) -> (-24.2898, 150.6299)
  line L31 (-24.2898, 150.6299) -> (-24.2891, 150.6293)
  line L32 (-24.0766, 150.4751) -> (-24.2891, 150.6293)
  line L33 (-24.9677, 149.6544) -> (-24.7493, 149.5087)
  line L34 (-24.9684, 149.6549) -> (-24.9677, 149.6544)
  curve K17 (-26.8949, 150.3396) -> (-24.9684, 149.6549)
  curve K18 (-27.412, 149.5101) -> (-25.9488, 148.082)
  line L35 (-25.9488, 148.082) -> (-25.948, 148.0816)
  line L36 (-25.721, 147.9497) -> (-25.948, 148.0816)
  line L37 (-26.5245, 147.043) -> (-26.2924, 146.9202)
  line L38 (-26.5252, 147.0434) -> (-26.5245, 147.043)
  curve K19 (-28.5112, 147.5297) -> (-26.5252, 147.0434)
  curve K20 (-28.9416, 146.6522) -> (-27.3414, 145.3795)
  line L39 (-27.3414, 145.3795) -> (-27.3407, 145.3791)
  line L40 (-27.1015, 145.2708) -> (-27.3407, 145.3791)
  line L41 (-27.8091, 144.2875) -> (-27.5658, 144.1888)
  line L42 (-27.8099, 144.2878) -> (-27.8091, 144.2875)
  curve K21 (-29.8348, 144.5708) -> (-27.8099, 144.2878)
  curve K22 (-30.1743, 143.6542) -> (-28.4536, 142.5499)
  line L43 (-28.4536, 142.5499) -> (-28.4528, 142.5496)
  line L44 (-28.2038, 142.466) -> (-28.4528, 142.5496)
  line L45 (-28.8084, 141.4162) -> (-28.5563, 141.3426)
  line L46 (-28.8092, 141.4164) -> (-28.8084, 141.4162)
  curve K23 (-30.8524, 141.493) -> (-28.8092, 141.4164)
  curve K24 (-31.0973, 140.5468) -> (-29.2737, 139.6223)
  line L47 (-29.2737, 139.6223) -> (-29.2729, 139.6221)
  line L48 (-29.0168, 139.5641) -> (-29.2729, 139.6221)
  line L49 (-29.512, 138.4585) -> (-29.2538, 138.4108)
  line L50 (-29.5129, 138.4587) -> (-29.512, 138.4585)
  curve K25 (-31.5533, 138.3282) -> (-29.5129, 138.4587)
  curve K26 (-31.7013, 137.3621) -> (-29.7935, 136.6267)
  line L51 (-29.7935, 136.6267) -> (-29.7927, 136.6266)
  line L52 (-29.532, 136.5949) -> (-29.7927, 136.6266)
  line L53 (-29.9128, 135.4448) -> (-29.6511, 135.4235)
  line L54 (-29.9137, 135.4449) -> (-29.9128, 135.4448)
  curve K27 (-31.9304, 135.1087) -> (-29.9137, 135.4449)
  curve K28 (-31.98, 134.1325) -> (-30.0076, 133.594)
  line L55 (-30.0076, 133.594) -> (-30.0067, 133.5939)
  line L56 (-29.7442, 133.5887) -> (-30.0067, 133.5939)
  line L57 (-30.0067, 132.4061) -> (-29.7442, 132.4113)
  line L58 (-30.0076, 132.4061) -> (-30.0067, 132.4061)
  curve K29 (-31.98, 131.8675) -> (-30.0076, 132.4061)
  curve K30 (-31.9304, 130.8913) -> (-29.9137, 130.5551)
  line L59 (-29.9137, 130.5551) -> (-29.9128, 130.5552)
  line L60 (-29.6511, 130.5765) -> (-29.9128, 130.5552)
  line L61 (-29.7927, 129.3734) -> (-29.532, 129.4051)
  line L62 (-29.7935, 129.3733) -> (-29.7927, 129.3734)
  curve K31 (-31.7013, 128.6379) -> (-29.7935, 129.3733)
  curve K32 (-31.5533, 127.6718) -> (-29.5129, 127.5413)
  line L63 (-29.5129, 127.5413) -> (-29.512, 127.5415)
  line L64 (-29.2538, 127.5892) -> (-29.512, 127.5415)
  line L65 (-29.2729, 126.3779) -> (-29.0168, 126.4359)
  line L66 (-29.2737, 126.3777) -> (-29.2729, 126.3779)
  curve K33 (-31.0973, 125.4532) -> (-29.2737, 126.3777)
  curve K34 (-30.8524, 124.507) -> (-28.8092, 124.5836)
  line L67 (-28.8092, 124.5836) -> (-28.8084, 124.5838)
  line L68 (-28.5563, 124.6574) -> (-28.8084, 124.5838)
  line L69 (-28.4528, 123.4504) -> (-28.2038, 123.534)
  line L70 (-28.4536, 123.4501) -> (-28.4528, 123.4504)
  curve K35 (-30.1743, 122.3458) -> (-28.4536, 123.4501)
  curve K36 (-29.8348, 121.4292) -> (-27.8099, 121.7122)
  line L71 (-27.8099, 121.7122) -> (-27.8091, 121.7125)
  line L72 (-27.5658, 121.8112) -> (-27.8091, 121.7125)
  line L73 (-27.3407, 120.6209) -> (-27.1015, 120.7292)
  line L74 (-27.3414, 120.6205) -> (-27.3407, 120.6209)
  curve K37 (-28.9416, 119.3478) -> (-27.3414, 120.6205)
  curve K38 (-28.5112, 118.4703) -> (-26.5252, 118.9566)
  line L75 (-26.5252, 118.9566) -> (-26.5245, 118.957)
  line L76 (-26.2924, 119.0799) -> (-26.5245, 118.957)
  line L77 (-25.948, 117.9184) -> (-25.721, 118.0503)
  line L78 (-25.9488, 117.918) -> (-25.948, 117.9184)
  curve K39 (-27.412, 116.4899) -> (-25.9488, 117.918)
  curve K40 (-26.8949, 115.6604) -> (-24.9684, 116.3451)
  line L79 (-24.9684, 116.3451) -> (-24.9677, 116.3456)
  line L80 (-24.7493, 116.4913) -> (-24.9677, 116.3456)
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  dimension "d216" diameter = 6.1
  dimension "d217" diameter = 9
extrude "Extrude1" new body sketch "Sketch1" along normal blind 16 bodies "Motor_sleeve"
sketch "Sketch2" plane through (0, 0, 0) normal (0, 1, 0) x axis (1, 0, 0)
  line L1 (22, -128.5) -> (22, -133)
  line L2 (22, -133) -> (22, -137.5)
  line L3 (6, -128.5) -> (6, -133)
  line L4 (6, -133) -> (6, -137.5)
  line L5 (22, -137.5) -> (6, -137.5)
  line L6 (22, -128.5) -> (6, -128.5)
  line L7 (10, -130) -> (10, -133)
  line L8 (10, -133) -> (10, -136)
  line L9 (23, -127.1) -> (23, -130)
  line L10 (23, -136) -> (23, -138.9)
  line L11 (45, -114.6) -> (45, -116.1)
  line L12 (45, -149.9) -> (45, -151.4)
  line L13 (27, -114.6) -> (27, -127.1)
  line L14 (27, -138.9) -> (27, -151.4)
  line L15 (67.5, -116.1) -> (67.5, -133)
  line L16 (67.5, -133) -> (67.5, -149.9)
  line L17 (23, -136) -> (10, -136)
  line L18 (23, -130) -> (10, -130)
  line L19 (27, -138.9) -> (23, -138.9)
  line L20 (27, -127.1) -> (23, -127.1)
  line L21 (45, -151.4) -> (27, -151.4)
  line L22 (45, -114.6) -> (27, -114.6)
  line L23 (67.5, -149.9) -> (45, -149.9)
  line L24 (67.5, -116.1) -> (45, -116.1)
  line L25 (14, -136) -> (10, -136)
  line L26 (15.5, -139.5) -> (14, -139.5)
  line L27 (17, -128.5) -> (17, -130)
  line L28 (14, -126.5) -> (15.5, -126.5)
  line L29 (14, -139.5) -> (14, -126.5)
  line L30 (15.5, -140.5) -> (15.5, -126)
  line L31 (15.5, -126.5) -> (15.5, -139.5)
  point P10 (10, -136)
  point P26 (10, -136)
  point P32 (15.5, -139.5)
  point P33 (17, -130)
  point P34 (17, -128.5)
  point P35 (15.5, -126.5)
  point P27 (14, -136)
  point P28 (14, -139.5)
  point P29 (14, -126.5)
  coincident P10 P26
  perpendicular L8 L25
  horizontal L26
  vertical L27
  horizontal L28
  vertical L29
  perpendicular L26 L30
  coincident L30 P32
  coincident L18 P33
  coincident L6 P34
  coincident L30 P35
  dimension "d220" distance P26 P27 = 4
  dimension "d222" distance P28 P29 = 13
work_plane "WorkPlane1"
